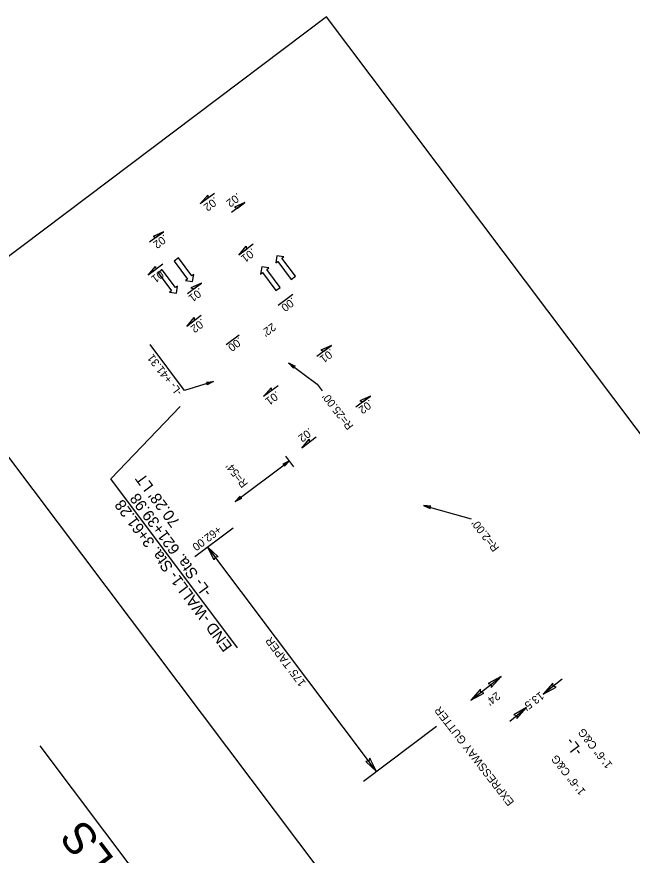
# Model space of a CAD drawing. Extents: x 1263113 to 1265001, y 775064 to 777068.
# Drawn here: x 1263498 to 1263883, y 775951 to 776475 of the extents above; entities that cross this region are included whole.
import ezdxf

# ---------------------------------------------------------------- set-up
doc = ezdxf.new("R2010")
doc.units = 0
for name, color, linetype in [('Default', 7, 'Continuous'), ('Prop Dimension', 7, 'Continuous'), ('Prop Dimension Text', 7, 'Continuous'), ('Prop Horizontal Alignment Curve and Spiral Data', 7, 'Continuous'), ('Prop Horizontal Alignment Direction Label', 7, 'Continuous'), ('Prop Horizontal Alignment Station Label', 7, 'Continuous'), ('Prop Lane Arrow CELL', 7, 'Continuous'), ('Prop Superelevation  Arrow CELL', 7, 'Continuous'), ('Prop Superelevation Label', 7, 'Continuous'), ('Prop Terminator CELL', 7, 'Continuous'), ('Sheet Typical CELL', 7, 'Continuous')]:
    doc.layers.add(name, color=color, linetype=linetype)

msp = doc.modelspace()

# ---------------------------------------------------------------- linework, layer by layer
at = {"layer": 'Default'}
for p, q in [((1263671.37, 776193.59), (1263666.37, 776200.23)), ((1263634.8, 776171.89), (1263668.65, 776197.2))]:
    msp.add_line(p, q, dxfattribs=at)
at = {"layer": 'Prop Dimension'}
for p, q in [((1263603.08, 776241.33), (1263581.5, 776269.99)), ((1263668.11, 776258.5), (1263685.94, 776245.21)), ((1263621.26, 776246.93), (1263603.08, 776241.33)), ((1263685.97, 776245.16), (1263689.17, 776240.92)), ((1263752.45, 776169.41), (1263782.28, 776161.13))]:
    msp.add_line(p, q, dxfattribs=at)
at = {"layer": 'Prop Dimension Text'}
for p, q in [((1263633.43, 776155.22), (1263609.54, 776137.23)), ((1263723, 776003.22), (1263617.53, 776143.25)), ((1263781.99, 776047.77), (1263800.97, 776062.46)), ((1263839.1, 776060.89), (1263827.36, 776051.44)), ((1263806.5, 776034.65), (1263816.93, 776043.04)), ((1263715.01, 775997.21), (1263760.54, 776031.5))]:
    msp.add_line(p, q, dxfattribs=at)
for points in [[(1263621.49, 776135.37), (1263617.31, 776143.49), (1263624.04, 776137.22), (1263622.07, 776137.18)], [(1263794.8, 776055.72), (1263800.97, 776062.46), (1263792.83, 776058.18), (1263794.72, 776057.62)], [(1263833.4, 776058.29), (1263827.36, 776051.44), (1263835.41, 776055.87), (1263833.52, 776056.39)], [(1263788.16, 776054.5), (1263781.99, 776047.77), (1263790.12, 776052.04), (1263788.24, 776052.6)], [(1263810.89, 776036.19), (1263816.93, 776043.04), (1263808.88, 776038.62), (1263810.77, 776038.09)], [(1263716.35, 776009.48), (1263723, 776003.22), (1263718.83, 776011.41), (1263718.25, 776009.53)]]:
    msp.add_lwpolyline(points, close=True, dxfattribs=at)
at = {"layer": 'Prop Horizontal Alignment Curve and Spiral Data'}
msp.add_line((1263747.97, 775706.98), (1263512.82, 776019.17), dxfattribs=at)
at = {"layer": 'Prop Horizontal Alignment Station Label'}
for p in [(1263600.36, 776231.29), (1263636.22, 776080.46)]:
    msp.add_line(p, (1263556.91, 776186.07), dxfattribs=at)
at = {"layer": 'Prop Lane Arrow CELL'}
for p, q in [((1263599.19, 776324.06), (1263596.55, 776322.08)), ((1263596.55, 776322.08), (1263604.94, 776310.88)), ((1263607.58, 776312.86), (1263599.19, 776324.06)), ((1263660.81, 776325.4), (1263660.14, 776320.96)), ((1263660.14, 776320.96), (1263661.34, 776321.86)), ((1263665.18, 776324.74), (1263660.81, 776325.4)), ((1263661.34, 776321.86), (1263669.74, 776310.66)), ((1263663.98, 776323.84), (1263665.18, 776324.74)), ((1263672.38, 776312.63), (1263663.98, 776323.84)), ((1263589.11, 776316.69), (1263586.47, 776314.71)), ((1263597.51, 776305.49), (1263589.11, 776316.69)), ((1263651.3, 776318.45), (1263650.63, 776314.01)), ((1263655.67, 776317.79), (1263651.3, 776318.45)), ((1263654.47, 776316.89), (1263655.67, 776317.79)), ((1263662.87, 776305.69), (1263654.47, 776316.89)), ((1263586.47, 776314.71), (1263594.87, 776303.51)), ((1263604.94, 776310.88), (1263603.74, 776309.98)), ((1263603.74, 776309.98), (1263608.11, 776309.32)), ((1263608.79, 776313.76), (1263607.58, 776312.86)), ((1263608.11, 776309.32), (1263608.79, 776313.76)), ((1263650.63, 776314.01), (1263651.83, 776314.91)), ((1263651.83, 776314.91), (1263660.22, 776303.71)), ((1263669.74, 776310.66), (1263672.38, 776312.63)), ((1263598.71, 776306.39), (1263597.51, 776305.49)), ((1263598.04, 776301.95), (1263598.71, 776306.39)), ((1263660.22, 776303.71), (1263662.87, 776305.69)), ((1263594.87, 776303.51), (1263593.67, 776302.61)), ((1263593.67, 776302.61), (1263598.04, 776301.95))]:
    msp.add_line(p, q, dxfattribs=at)
at = {"layer": 'Prop Superelevation  Arrow CELL'}
for points in [[(1263612.89, 776357.78), (1263617.52, 776363.27), (1263617.61, 776361.33)], [(1263612.89, 776357.78), (1263617.52, 776363.27), (1263617.61, 776361.33)], [(1263640.83, 776358.79), (1263634.28, 776355.86), (1263636.12, 776355.24)], [(1263640.83, 776358.79), (1263634.28, 776355.86), (1263636.12, 776355.24)], [(1263589.91, 776340.47), (1263583.36, 776337.53), (1263585.2, 776336.92)], [(1263637, 776325.86), (1263641.63, 776331.35), (1263641.71, 776329.41)], [(1263637, 776325.86), (1263641.63, 776331.35), (1263641.71, 776329.41)], [(1263580.37, 776313.25), (1263585, 776318.74), (1263585.08, 776316.8)], [(1263613.64, 776308.26), (1263607.09, 776305.33), (1263608.93, 776304.71)], [(1263604.45, 776281.31), (1263609.08, 776286.8), (1263609.16, 776284.86)], [(1263604.45, 776281.31), (1263609.08, 776286.8), (1263609.16, 776284.86)], [(1263694.89, 776269.3), (1263688.33, 776266.37), (1263690.17, 776265.75)], [(1263694.89, 776269.3), (1263688.33, 776266.37), (1263690.17, 776265.75)], [(1263652.5, 776237.38), (1263657.13, 776242.87), (1263657.21, 776240.93)], [(1263652.5, 776237.38), (1263657.13, 776242.87), (1263657.21, 776240.93)], [(1263719.28, 776237.6), (1263712.73, 776234.67), (1263714.57, 776234.05)], [(1263719.28, 776237.6), (1263712.73, 776234.67), (1263714.57, 776234.05)], [(1263676.35, 776205.26), (1263680.97, 776210.75), (1263681.06, 776208.81)]]:
    msp.add_lwpolyline(points, close=True, dxfattribs=at)
at = {"layer": 'Prop Superelevation Label'}
for p, q in [((1263621.69, 776364.4), (1263612.89, 776357.78)), ((1263640.83, 776358.79), (1263632.36, 776352.41)), ((1263589.91, 776340.47), (1263581.09, 776333.82)), ((1263646.03, 776332.66), (1263636.96, 776325.83)), ((1263589.48, 776320.11), (1263580.41, 776313.28)), ((1263613.64, 776308.26), (1263604.9, 776301.68)), ((1263670.73, 776301.18), (1263661.65, 776294.35)), ((1263613.52, 776288.14), (1263604.45, 776281.31)), ((1263637.16, 776275.9), (1263629.06, 776269.8)), ((1263694.89, 776269.3), (1263685.81, 776262.47)), ((1263661.57, 776244.21), (1263652.5, 776237.38)), ((1263719.28, 776237.6), (1263710.21, 776230.77)), ((1263685.42, 776212.1), (1263676.35, 776205.26))]:
    msp.add_line(p, q, dxfattribs=at)
at = {"layer": 'Prop Terminator CELL'}
for points in [[(1263671.25, 776255.19), (1263668.11, 776258.5), (1263672.21, 776256.44), (1263671.27, 776256.14)], [(1263616.73, 776246.34), (1263621.26, 776246.93), (1263617.17, 776244.83), (1263617.48, 776245.76)], [(1263665.51, 776193.89), (1263668.65, 776197.2), (1263664.54, 776195.13), (1263665.48, 776194.84)], [(1263637.94, 776175.21), (1263634.8, 776171.89), (1263638.9, 776173.96), (1263637.96, 776174.26)], [(1263756.99, 776168.95), (1263752.45, 776169.41), (1263756.59, 776167.43), (1263756.25, 776168.35)]]:
    msp.add_lwpolyline(points, close=True, dxfattribs=at)
at = {"layer": 'Sheet Typical CELL'}
msp.add_lwpolyline([(1263432.63, 776279.56), (1264082.63, 775416.59), (1264341.8, 775611.8), (1263691.81, 776474.77)], close=True, dxfattribs=at)

# ---------------------------------------------------------------- texts
at = {"layer": 'Prop Dimension Text'}
for s, rotation, p in [("22'", 216.9874, (1263657.86, 776283.73)), ('-L- +41.31', 127.7256, (1263602.02, 776240.25)), ("R=25.00'", 127.7256, (1263708.97, 776219.1)), ("R=54'", 127.7256, (1263643, 776182.89)), ("R=2.00'", 127.7256, (1263800.1, 776142.93)), ('+62.00', 216.9874, (1263623.88, 776157.01)), ("175' TAPER", 126.9874, (1263679.19, 776058.55)), ("24'", 216.9874, (1263798.12, 776053.2)), ("13.5'", 216.9874, (1263825.51, 776053.33)), ('EXPRESSWAY GUTTER', 127.7256, (1263809.43, 775984.09)), ('1\'-6" C&G', 128.2862, (1263870.85, 776007.42)), ('1\'-6" C&G', 128.2862, (1263854.11, 775990.78))]:
    msp.add_text(s, height=5, rotation=rotation, dxfattribs=at).set_placement(p)
at = {"layer": 'Prop Horizontal Alignment Curve and Spiral Data'}
msp.add_text('INTERSECTION DETAILS', height=20, rotation=126.9874, dxfattribs=at).set_placement((1263731.35, 775720.21))
at = {"layer": 'Prop Horizontal Alignment Direction Label'}
msp.add_text('-L-', height=7, rotation=126.9852, dxfattribs=at).set_placement((1263852.4, 776015.86))
at = {"layer": 'Prop Horizontal Alignment Station Label'}
for s, p in [("70.28' LT", (1263600.59, 776159.07)), ('-L- Sta. 621+39.98', (1263620.43, 776115.37)), ('END -WALL1- Sta. 3+61.28', (1263633.27, 776081.36))]:
    msp.add_text(s, height=7, rotation=126.6786, dxfattribs=at).set_placement(p)
at = {"layer": 'Prop Superelevation Label'}
for s, p in [('.02', (1263636.07, 776364.95)), ('.02', (1263621.91, 776362.44)), ('.02', (1263590.31, 776339.07)), ('.01', (1263645.29, 776330.42)), ('.01', (1263589.18, 776317.63)), ('.01', (1263612.49, 776305.62)), ('.00', (1263670.37, 776299.68)), ('.02', (1263613.78, 776286.44)), ('.00', (1263637.07, 776274.81)), ('.01', (1263694.48, 776267.57)), ('.01', (1263660.45, 776241.19)), ('.02', (1263718.73, 776235.77)), ('.02', (1263681.05, 776218.1))]:
    msp.add_text(s, height=5, rotation=217.2584, dxfattribs=at).set_placement(p)

doc.saveas('drawing.dxf')
